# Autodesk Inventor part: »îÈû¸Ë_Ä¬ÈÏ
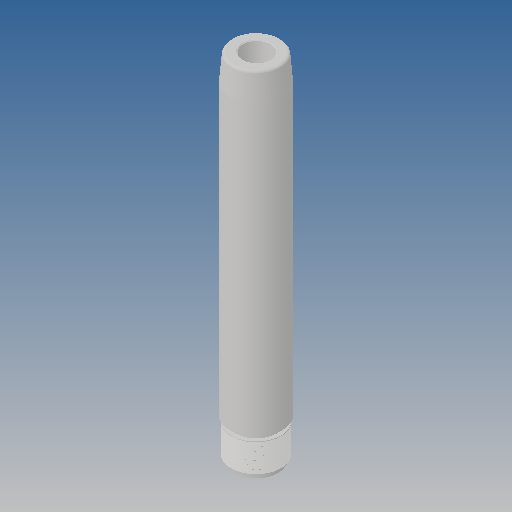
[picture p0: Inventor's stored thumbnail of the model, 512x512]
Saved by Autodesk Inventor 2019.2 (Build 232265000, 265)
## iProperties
Created: 2012-03
Part Number: »îÈû¸Ë_Ä¬ÈÏ
Material: Ogólny
Document SubType Name: Modeling
Designer: CADENGINEERING4
Density: 1 g/cm^3
Appearance: Domyślna
Author: CADENGINEERING4
Revision Number: ÈÎºÎ
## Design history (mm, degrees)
feature "NONE"
node "Bryła1"
